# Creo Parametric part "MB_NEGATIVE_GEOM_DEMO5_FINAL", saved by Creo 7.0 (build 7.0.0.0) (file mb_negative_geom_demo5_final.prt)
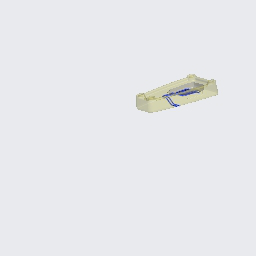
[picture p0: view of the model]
Units: millimeter Kilogram Sec (mmKs); MM, KILOGRAM, SECS

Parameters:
  COPY_GEOM_ORIGIN_TYPE = "Part"

Created from: MB_NEGATIVE_GEOM_DEMO5.PRT

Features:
  1. datum plane "RIGHT"
  2. datum plane "TOP"
  3. datum plane "FRONT"
  4. datum axis
  5. coordinate system
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
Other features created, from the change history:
  planar section "XSEC0002" (2 times)
  protrusion "Sweep 1" (4 times)
  feature "Body Subtract 8" (4 times)
  planar section "XSEC0001" (3 times)
  datum plane "DTM9"
  feature "Move 1"
  feature "Copy 1"
  patch "Solidify 1"

Other named items: SIDE_POCKET, CURVE_BODY_INTERSECT, TOP_POCKET, LOCAL_GROUP_16, LOCAL_GROUP_58, LOCAL_GROUP_44, LOCAL_GROUP_30, LOCAL_GROUP_15, LOCAL_GROUP, LOCAL_GROUP_59, LOCAL_GROUP_45, LOCAL_GROUP_31, LOCAL_GROUP_17, LOCAL_GROUP_1, LOCAL_GROUP_60, LOCAL_GROUP_46, LOCAL_GROUP_32, LOCAL_GROUP_18, LOCAL_GROUP_2, LOCAL_GROUP_61, LOCAL_GROUP_47, LOCAL_GROUP_33, LOCAL_GROUP_19, LOCAL_GROUP_3, LOCAL_GROUP_62, LOCAL_GROUP_48, LOCAL_GROUP_34, LOCAL_GROUP_20, LOCAL_GROUP_4, LOCAL_GROUP_63, LOCAL_GROUP_49, LOCAL_GROUP_35, LOCAL_GROUP_21, LOCAL_GROUP_5, LOCAL_GROUP_64, LOCAL_GROUP_50, LOCAL_GROUP_36, LOCAL_GROUP_22, LOCAL_GROUP_6, LOCAL_GROUP_7, LOCAL_GROUP_65, LOCAL_GROUP_51, LOCAL_GROUP_37, LOCAL_GROUP_23, LOCAL_GROUP_8, LOCAL_GROUP_66, LOCAL_GROUP_52, LOCAL_GROUP_38, LOCAL_GROUP_24, LOCAL_GROUP_9, LOCAL_GROUP_67, LOCAL_GROUP_53, LOCAL_GROUP_39, LOCAL_GROUP_25, LOCAL_GROUP_10, LOCAL_GROUP_68, LOCAL_GROUP_54, LOCAL_GROUP_40, LOCAL_GROUP_26, LOCAL_GROUP_11, LOCAL_GROUP_69, LOCAL_GROUP_55, LOCAL_GROUP_41, LOCAL_GROUP_27, LOCAL_GROUP_12, LOCAL_GROUP_70, LOCAL_GROUP_56, LOCAL_GROUP_42, LOCAL_GROUP_28, LOCAL_GROUP_13, LOCAL_GROUP_71, LOCAL_GROUP_57, LOCAL_GROUP_43, LOCAL_GROUP_29, LOCAL_GROUP_14, MAIN_BODY, COMPOSITE_PIPE_CURVE, PIPE_CURVE_BACKUP_FROZEN, MAIN, POCKET_INSERT, CURVE_BASE1, CAVITY, ALL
